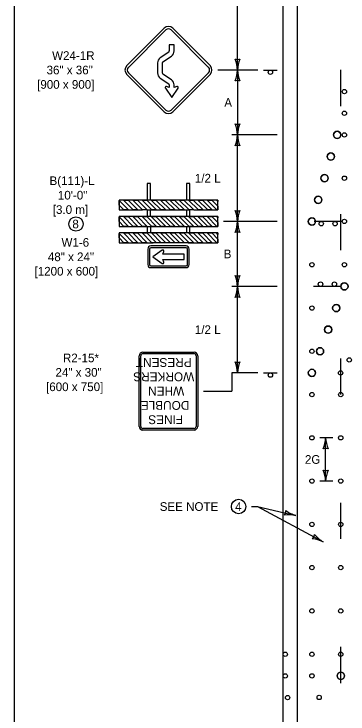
# Model space of a CAD drawing. Extents: x 49991.4 to 50021, y 49987.6 to 50011.4.
# Drawn here: x 50000.336 to 50002.651, y 50003.757 to 50008.61 of the extents above; entities that cross this region are included whole.
import ezdxf

# ---------------------------------------------------------------- set-up
doc = ezdxf.new("R2010")
doc.units = 0
for name, color, linetype in [('Level 1', 7, 'Continuous'), ('Level 2', 7, 'Continuous'), ('Level 3', 7, 'Continuous')]:
    doc.layers.add(name, color=color, linetype=linetype)

msp = doc.modelspace()

# ---------------------------------------------------------------- linework, layer by layer
at = {"layer": 'Level 1'}
for p, q in [((50002.201, 50000.5714), (50002.201, 50010.7538)), ((50002.301, 50000.5714), (50002.301, 50010.7538)), ((50001.4455, 50008.3968), (50001.412, 50008.3968)), ((50001.412, 50008.3968), (50001.412, 50008.3543)), ((50001.4455, 50008.3533), (50001.4455, 50008.3968)), ((50001.4078, 50008.3459), (50001.3492, 50008.3061)), ((50001.3681, 50008.2784), (50001.4267, 50008.3182)), ((50001.3304, 50008.2705), (50001.3305, 50008.2007)), ((50001.364, 50008.2007), (50001.3639, 50008.2705)), ((50001.4264, 50008.1537), (50001.3681, 50008.1928)), ((50002.065, 50008.2213), (50002.161, 50008.2213)), ((50002.601, 50007.9716), (50002.601, 50008.2216)), ((50001.3495, 50008.165), (50001.4078, 50008.1259)), ((50001.3847, 50008.096), (50001.4287, 50008.0319)), ((50001.412, 50008.1), (50001.3922, 50008.1062)), ((50001.412, 50008.118), (50001.412, 50008.1)), ((50001.4287, 50008.0319), (50001.4728, 50008.096)), ((50001.4455, 50008.1), (50001.4455, 50008.118)), ((50001.4653, 50008.1062), (50001.4455, 50008.1)), ((50001.0644, 50007.317), (50001.1302, 50007.2511)), ((50001.0644, 50007.317), (50001.1302, 50007.2511)), ((50001.0941, 50007.3195), (50001.1625, 50007.2511)), ((50001.1625, 50007.2511), (50001.0941, 50007.3195)), ((50001.1263, 50007.3195), (50001.1947, 50007.2511)), ((50001.1263, 50007.3195), (50001.1947, 50007.2511)), ((50001.1585, 50007.3195), (50001.2269, 50007.2511)), ((50001.2269, 50007.2511), (50001.1585, 50007.3195)), ((50001.1908, 50007.3195), (50001.2592, 50007.2511)), ((50001.1908, 50007.3195), (50001.2592, 50007.2511)), ((50001.223, 50007.3195), (50001.2914, 50007.2511)), ((50001.2914, 50007.2511), (50001.223, 50007.3195)), ((50001.2553, 50007.3195), (50001.3237, 50007.2511)), ((50001.2553, 50007.3195), (50001.3237, 50007.2511)), ((50001.2875, 50007.3195), (50001.3559, 50007.2511)), ((50001.3559, 50007.2511), (50001.2875, 50007.3195)), ((50001.3197, 50007.3195), (50001.3881, 50007.2511)), ((50001.3197, 50007.3195), (50001.3881, 50007.2511)), ((50001.3519, 50007.3195), (50001.4203, 50007.2511)), ((50001.4203, 50007.2511), (50001.3519, 50007.3195)), ((50001.3842, 50007.3195), (50001.4526, 50007.2511)), ((50001.3842, 50007.3195), (50001.4526, 50007.2511)), ((50001.4165, 50007.3195), (50001.4849, 50007.2511)), ((50001.4849, 50007.2511), (50001.4165, 50007.3195)), ((50001.4487, 50007.3195), (50001.5171, 50007.2511)), ((50001.4487, 50007.3195), (50001.5171, 50007.2511)), ((50001.4809, 50007.3195), (50001.5493, 50007.2511)), ((50001.5493, 50007.2511), (50001.4809, 50007.3195)), ((50001.5131, 50007.3195), (50001.5815, 50007.2511)), ((50001.5131, 50007.3195), (50001.5815, 50007.2511)), ((50001.5454, 50007.3195), (50001.6138, 50007.2511)), ((50001.6138, 50007.2511), (50001.5454, 50007.3195)), ((50001.5777, 50007.3195), (50001.6461, 50007.2511)), ((50001.5777, 50007.3195), (50001.6461, 50007.2511)), ((50001.6099, 50007.3195), (50001.6783, 50007.2511)), ((50001.6783, 50007.2511), (50001.6099, 50007.3195)), ((50001.6421, 50007.3195), (50001.7105, 50007.2511)), ((50001.6421, 50007.3195), (50001.7105, 50007.2511)), ((50001.6744, 50007.3195), (50001.7428, 50007.2511)), ((50001.7428, 50007.2511), (50001.6744, 50007.3195)), ((50001.7066, 50007.3195), (50001.7484, 50007.2778)), ((50001.7066, 50007.3195), (50001.7484, 50007.2778)), ((50001.7389, 50007.3195), (50001.7484, 50007.31)), ((50001.7484, 50007.31), (50001.7389, 50007.3195)), ((50001.0644, 50007.2847), (50001.098, 50007.2511)), ((50001.098, 50007.2511), (50001.0644, 50007.2847)), ((50002.601, 50006.9716), (50002.601, 50007.2216)), ((50001.0644, 50007.203), (50001.1302, 50007.1372)), ((50001.0644, 50007.203), (50001.1302, 50007.1372)), ((50001.0644, 50007.1708), (50001.098, 50007.1372)), ((50001.098, 50007.1372), (50001.0644, 50007.1708)), ((50001.0941, 50007.2056), (50001.1625, 50007.1372)), ((50001.1625, 50007.1372), (50001.0941, 50007.2056)), ((50001.1263, 50007.2056), (50001.1947, 50007.1372)), ((50001.1263, 50007.2056), (50001.1947, 50007.1372)), ((50001.1585, 50007.2056), (50001.2269, 50007.1372)), ((50001.2269, 50007.1372), (50001.1585, 50007.2056)), ((50001.1908, 50007.2056), (50001.2592, 50007.1372)), ((50001.1908, 50007.2056), (50001.2592, 50007.1372)), ((50001.223, 50007.2056), (50001.2914, 50007.1372)), ((50001.2553, 50007.2056), (50001.3237, 50007.1372)), ((50001.2875, 50007.2056), (50001.3559, 50007.1372)), ((50001.3197, 50007.2056), (50001.3881, 50007.1372)), ((50001.3519, 50007.2056), (50001.4203, 50007.1372)), ((50001.3842, 50007.2056), (50001.4526, 50007.1372)), ((50001.4165, 50007.2056), (50001.4849, 50007.1372)), ((50001.4487, 50007.2056), (50001.5171, 50007.1372)), ((50001.4809, 50007.2056), (50001.5432, 50007.1433)), ((50001.5131, 50007.2056), (50001.5432, 50007.1755)), ((50001.5432, 50007.1755), (50001.5815, 50007.1372)), ((50001.5454, 50007.2056), (50001.6138, 50007.1372)), ((50001.6138, 50007.1372), (50001.5454, 50007.2056)), ((50001.5777, 50007.2056), (50001.6461, 50007.1372)), ((50001.5777, 50007.2056), (50001.6461, 50007.1372)), ((50001.6099, 50007.2056), (50001.6783, 50007.1372)), ((50001.6783, 50007.1372), (50001.6099, 50007.2056)), ((50001.6421, 50007.2056), (50001.7105, 50007.1372)), ((50001.6421, 50007.2056), (50001.7105, 50007.1372)), ((50001.6744, 50007.2056), (50001.7428, 50007.1372)), ((50001.7428, 50007.1372), (50001.6744, 50007.2056)), ((50001.7066, 50007.2056), (50001.7484, 50007.1638)), ((50001.7066, 50007.2056), (50001.7484, 50007.1638)), ((50001.7389, 50007.2056), (50001.7484, 50007.1961)), ((50001.7484, 50007.1961), (50001.7389, 50007.2056)), ((50002.5135, 50007.1714), (50002.4175, 50007.1714)), ((50002.6095, 50007.1714), (50002.5135, 50007.1714)), ((50001.281, 50007.1372), (50001.281, 50007.0916)), ((50001.5318, 50007.1372), (50001.5318, 50007.0916)), ((50001.5432, 50007.1433), (50001.5493, 50007.1372)), ((50001.0644, 50007.0891), (50001.1302, 50007.0232)), ((50001.0644, 50007.0891), (50001.1302, 50007.0232)), ((50001.0941, 50007.0916), (50001.1625, 50007.0232)), ((50001.1625, 50007.0232), (50001.0941, 50007.0916)), ((50001.1263, 50007.0916), (50001.1947, 50007.0232)), ((50001.1263, 50007.0916), (50001.1947, 50007.0232)), ((50001.1585, 50007.0916), (50001.2269, 50007.0232)), ((50001.2269, 50007.0232), (50001.1585, 50007.0916)), ((50001.1908, 50007.0916), (50001.2592, 50007.0232)), ((50001.1908, 50007.0916), (50001.2592, 50007.0232)), ((50001.223, 50007.0916), (50001.2914, 50007.0232)), ((50001.2553, 50007.0916), (50001.3237, 50007.0232)), ((50001.2877, 50007.0916), (50001.3561, 50007.0232)), ((50001.3199, 50007.0916), (50001.3883, 50007.0232)), ((50001.3521, 50007.0916), (50001.4205, 50007.0232)), ((50001.3843, 50007.0916), (50001.4527, 50007.0232)), ((50001.4165, 50007.0916), (50001.4849, 50007.0232)), ((50001.4487, 50007.0916), (50001.5171, 50007.0232)), ((50001.4809, 50007.0916), (50001.5493, 50007.0232)), ((50001.5131, 50007.0916), (50001.5815, 50007.0232)), ((50001.5454, 50007.0916), (50001.6138, 50007.0232)), ((50001.6138, 50007.0232), (50001.5454, 50007.0916)), ((50001.5777, 50007.0916), (50001.6461, 50007.0232)), ((50001.5777, 50007.0916), (50001.6461, 50007.0232)), ((50001.6099, 50007.0916), (50001.6783, 50007.0232)), ((50001.6783, 50007.0232), (50001.6099, 50007.0916)), ((50001.6421, 50007.0916), (50001.7105, 50007.0232)), ((50001.6421, 50007.0916), (50001.7105, 50007.0232)), ((50001.6744, 50007.0916), (50001.7428, 50007.0232)), ((50001.7428, 50007.0232), (50001.6744, 50007.0916)), ((50001.7066, 50007.0916), (50001.7484, 50007.0498)), ((50001.7066, 50007.0916), (50001.7484, 50007.0498)), ((50001.7389, 50007.0916), (50001.7484, 50007.0821)), ((50001.7484, 50007.0821), (50001.7389, 50007.0916)), ((50001.0644, 50007.0568), (50001.098, 50007.0232)), ((50001.098, 50007.0232), (50001.0644, 50007.0568)), ((50001.2696, 50007.0232), (50001.3009, 50007.0232)), ((50001.5289, 50007.0232), (50001.2838, 50007.0232)), ((50001.5493, 50007.0232), (50001.5094, 50007.0232)), ((50001.2629, 50006.9805), (50001.2629, 50006.8722)), ((50001.2753, 50006.9805), (50001.2753, 50006.8722)), ((50001.5289, 50007.0014), (50001.2838, 50007.0014)), ((50001.5289, 50006.989), (50001.2838, 50006.989)), ((50001.3633, 50006.972), (50001.2969, 50006.9263)), ((50001.5375, 50006.8722), (50001.5375, 50006.9805)), ((50001.5499, 50006.8722), (50001.5499, 50006.9805)), ((50001.2969, 50006.9263), (50001.3633, 50006.8806)), ((50001.3675, 50006.9446), (50001.3739, 50006.9642)), ((50001.5159, 50006.9446), (50001.3675, 50006.9446)), ((50001.5159, 50006.9081), (50001.5159, 50006.9446)), ((50001.3739, 50006.8885), (50001.3675, 50006.9081)), ((50001.3675, 50006.9081), (50001.3777, 50006.9081)), ((50001.3777, 50006.9081), (50001.5159, 50006.9081)), ((50001.2838, 50006.8636), (50001.5289, 50006.8636)), ((50001.2838, 50006.8512), (50001.5289, 50006.8512)), ((50002.5085, 50006.7214), (50002.4125, 50006.7214)), ((50002.6045, 50006.7214), (50002.5085, 50006.7214)), ((50001.2292, 50006.2654), (50001.5836, 50006.2654)), ((50001.2292, 50006.2549), (50001.5836, 50006.2549)), ((50001.2039, 50005.7506), (50001.2039, 50006.2401)), ((50001.2144, 50005.7506), (50001.2144, 50006.2401)), ((50001.5984, 50006.2401), (50001.5984, 50005.7506)), ((50001.6089, 50006.2401), (50001.6089, 50005.7506)), ((50002.601, 50005.9716), (50002.601, 50006.2216)), ((50002.065, 50006.1214), (50002.161, 50006.1214)), ((50001.5836, 50005.7359), (50001.2292, 50005.7359)), ((50001.5836, 50005.7253), (50001.2292, 50005.7253)), ((50001.4064, 50005.7253), (50001.4064, 50005.7253)), ((50002.601, 50004.9716), (50002.601, 50005.2216)), ((50002.301, 50004.6448), (50002.301, 50004.6811)), ((50002.601, 50003.9716), (50002.601, 50004.2216))]:
    msp.add_line(p, q, dxfattribs=at)
msp.add_lwpolyline([(50008.6146, 50011.2628), (50000.3356, 50011.2628), (50000.3356, 50000.0624), (50008.6146, 50000.0624)], close=True, dxfattribs=at)
for points in [[(50001.1171, 50008.2515), (50001.3763, 50008.5106)], [(50001.1288, 50008.2399), (50001.3879, 50008.499)], [(50001.4249, 50008.499), (50001.684, 50008.2399)], [(50001.4365, 50008.5106), (50001.6956, 50008.2515)], [(50001.3763, 50007.9321), (50001.1171, 50008.1912)], [(50001.3879, 50007.9438), (50001.1288, 50008.2029)], [(50001.684, 50008.2029), (50001.4249, 50007.9438)], [(50001.6956, 50008.1912), (50001.4365, 50007.9321)], [(50001.281, 50007.3196), (50001.281, 50007.4336), (50001.2582, 50007.4336), (50001.2582, 50007.3196)], [(50001.5546, 50007.3196), (50001.5546, 50007.4336), (50001.5318, 50007.4336), (50001.5318, 50007.3196)], [(50001.5815, 50007.2511), (50001.7484, 50007.2511), (50001.7484, 50007.3195), (50001.0644, 50007.3195), (50001.0644, 50007.2511), (50001.2269, 50007.2511)], [(50001.0644, 50007.2847), (50001.0644, 50007.317)], [(50001.0941, 50007.3195), (50001.1263, 50007.3195)], [(50001.1585, 50007.3195), (50001.1908, 50007.3195)], [(50001.223, 50007.3195), (50001.2553, 50007.3195)], [(50001.2875, 50007.3195), (50001.3197, 50007.3195)], [(50001.3519, 50007.3195), (50001.3842, 50007.3195)], [(50001.4165, 50007.3195), (50001.4487, 50007.3195)], [(50001.4809, 50007.3195), (50001.5131, 50007.3195)], [(50001.5454, 50007.3195), (50001.5777, 50007.3195)], [(50001.6099, 50007.3195), (50001.6421, 50007.3195)], [(50001.6744, 50007.3195), (50001.7066, 50007.3195)], [(50001.7389, 50007.3195), (50001.7484, 50007.3195), (50001.7484, 50007.31)], [(50001.7484, 50007.2778), (50001.7484, 50007.2511), (50001.7428, 50007.2511)], [(50001.1302, 50007.2511), (50001.098, 50007.2511)], [(50001.1947, 50007.2511), (50001.1625, 50007.2511)], [(50001.2592, 50007.2511), (50001.2269, 50007.2511)], [(50001.2582, 50007.2511), (50001.2582, 50007.2056)], [(50001.2592, 50007.2511), (50001.5493, 50007.2511)], [(50001.281, 50007.2056), (50001.281, 50007.2511)], [(50001.3237, 50007.2511), (50001.2914, 50007.2511)], [(50001.3881, 50007.2511), (50001.3559, 50007.2511)], [(50001.4526, 50007.2511), (50001.4203, 50007.2511)], [(50001.5171, 50007.2511), (50001.4849, 50007.2511)], [(50001.5318, 50007.2511), (50001.5318, 50007.2056)], [(50001.5815, 50007.2511), (50001.5493, 50007.2511)], [(50001.5546, 50007.2056), (50001.5546, 50007.2511)], [(50001.6461, 50007.2511), (50001.6138, 50007.2511)], [(50001.7105, 50007.2511), (50001.6783, 50007.2511)], [(50001.5432, 50007.1372), (50001.7484, 50007.1372), (50001.7484, 50007.2056), (50001.0644, 50007.2056), (50001.0644, 50007.1372), (50001.5432, 50007.1372)], [(50001.0644, 50007.1708), (50001.0644, 50007.203)], [(50001.0941, 50007.2056), (50001.1263, 50007.2056)], [(50001.1585, 50007.2056), (50001.1908, 50007.2056)], [(50001.3237, 50007.1372), (50001.2914, 50007.1372), (50001.223, 50007.2056), (50001.2553, 50007.2056), (50001.3237, 50007.1372)], [(50001.3881, 50007.1372), (50001.3559, 50007.1372), (50001.2875, 50007.2056), (50001.3197, 50007.2056), (50001.3881, 50007.1372)], [(50001.4526, 50007.1372), (50001.4203, 50007.1372), (50001.3519, 50007.2056), (50001.3842, 50007.2056), (50001.4526, 50007.1372)], [(50001.5171, 50007.1372), (50001.4849, 50007.1372), (50001.4165, 50007.2056), (50001.4487, 50007.2056), (50001.5171, 50007.1372)], [(50001.4809, 50007.2056), (50001.5131, 50007.2056), (50001.5432, 50007.1755), (50001.5815, 50007.1372), (50001.5546, 50007.1372), (50001.5493, 50007.1372), (50001.5432, 50007.1433), (50001.4809, 50007.2056)], [(50001.5454, 50007.2056), (50001.5777, 50007.2056)], [(50001.6099, 50007.2056), (50001.6421, 50007.2056)], [(50001.6744, 50007.2056), (50001.7066, 50007.2056)], [(50001.7389, 50007.2056), (50001.7484, 50007.2056), (50001.7484, 50007.1961)], [(50001.7484, 50007.1638), (50001.7484, 50007.1372), (50001.7428, 50007.1372)], [(50001.1302, 50007.1372), (50001.098, 50007.1372)], [(50001.1947, 50007.1372), (50001.1625, 50007.1372)], [(50001.2592, 50007.1372), (50001.2269, 50007.1372)], [(50001.2582, 50007.1372), (50001.2582, 50007.0916)], [(50001.5546, 50007.0916), (50001.5546, 50007.1372)], [(50001.6461, 50007.1372), (50001.6138, 50007.1372)], [(50001.7105, 50007.1372), (50001.6783, 50007.1372)], [(50001.5432, 50007.0916), (50001.0644, 50007.0916), (50001.0644, 50007.0232), (50001.2696, 50007.0232)], [(50001.0644, 50007.0568), (50001.0644, 50007.0891)], [(50001.0941, 50007.0916), (50001.1263, 50007.0916)], [(50001.1585, 50007.0916), (50001.1908, 50007.0916)], [(50001.3237, 50007.0232), (50001.3009, 50007.0232), (50001.2914, 50007.0232), (50001.223, 50007.0916), (50001.2553, 50007.0916), (50001.3237, 50007.0232)], [(50001.3883, 50007.0232), (50001.3561, 50007.0232), (50001.2877, 50007.0916), (50001.3199, 50007.0916), (50001.3883, 50007.0232)], [(50001.4527, 50007.0232), (50001.4205, 50007.0232), (50001.3521, 50007.0916), (50001.3843, 50007.0916), (50001.4527, 50007.0232)], [(50001.5171, 50007.0232), (50001.5094, 50007.0232), (50001.4849, 50007.0232), (50001.4165, 50007.0916), (50001.4487, 50007.0916), (50001.5171, 50007.0232)], [(50001.4809, 50007.0916), (50001.5131, 50007.0916), (50001.5815, 50007.0232), (50001.5493, 50007.0232), (50001.4809, 50007.0916)], [(50001.5432, 50007.0232), (50001.7484, 50007.0232), (50001.7484, 50007.0916), (50001.5432, 50007.0916)], [(50001.5454, 50007.0916), (50001.5777, 50007.0916)], [(50001.6099, 50007.0916), (50001.6421, 50007.0916)], [(50001.6744, 50007.0916), (50001.7066, 50007.0916)], [(50001.7389, 50007.0916), (50001.7484, 50007.0916), (50001.7484, 50007.0821)], [(50001.1302, 50007.0232), (50001.098, 50007.0232)], [(50001.1947, 50007.0232), (50001.1625, 50007.0232)], [(50001.2592, 50007.0232), (50001.2269, 50007.0232)], [(50001.6461, 50007.0232), (50001.6138, 50007.0232)], [(50001.7105, 50007.0232), (50001.6783, 50007.0232)], [(50001.7484, 50007.0498), (50001.7484, 50007.0232), (50001.7428, 50007.0232)]]:
    msp.add_lwpolyline(points, dxfattribs=at)
for centre, radius in [((50002.113, 50008.2061), 0.0152), ((50002.626, 50008.0714), 0.015), ((50002.626, 50007.9214), 0.015), ((50002.576, 50007.7714), 0.025), ((50002.626, 50007.7714), 0.015), ((50002.5322, 50007.6214), 0.025), ((50002.4885, 50007.4714), 0.025), ((50002.626, 50007.4714), 0.015), ((50002.4447, 50007.3214), 0.025), ((50002.401, 50007.1714), 0.025), ((50002.4655, 50007.1561), 0.0152), ((50002.5615, 50007.1561), 0.0152), ((50002.626, 50007.1714), 0.015), ((50002.401, 50006.8714), 0.015), ((50002.626, 50006.8714), 0.015), ((50002.4605, 50006.7367), 0.0152), ((50002.5565, 50006.7367), 0.0152), ((50002.626, 50006.7214), 0.025), ((50002.401, 50006.5714), 0.015), ((50002.5697, 50006.5714), 0.025), ((50002.5135, 50006.4214), 0.025), ((50002.4572, 50006.2714), 0.025), ((50002.401, 50006.2714), 0.015), ((50002.6594, 50006.2114), 0.015), ((50002.401, 50006.1214), 0.025), ((50002.113, 50006.1061), 0.0152), ((50002.5995, 50006.1214), 0.015), ((50002.401, 50005.9714), 0.015), ((50002.601, 50005.9714), 0.015), ((50002.401, 50005.6714), 0.015), ((50002.601, 50005.6714), 0.015), ((50002.401, 50005.3714), 0.015), ((50002.601, 50005.3714), 0.015), ((50002.401, 50005.0714), 0.015), ((50002.601, 50005.0714), 0.015), ((50002.401, 50004.7714), 0.015), ((50002.601, 50004.7714), 0.015), ((50002.401, 50004.4714), 0.015), ((50002.601, 50004.4714), 0.015), ((50002.216, 50004.1706), 0.015), ((50002.401, 50004.1714), 0.015), ((50002.601, 50004.1714), 0.015), ((50002.216, 50004.0206), 0.015), ((50002.401, 50004.0214), 0.015), ((50002.601, 50004.0214), 0.025), ((50002.2327, 50003.8706), 0.015), ((50002.4511, 50003.8714), 0.015)]:
    msp.add_circle(centre, radius, dxfattribs=at)
for centre, radius, start, end in [((50001.4064, 50008.4805), 0.0426, 45, 135), ((50001.4064, 50008.4805), 0.0262, 45, 135), ((50001.4025, 50008.3538), 0.00951, 304.2095, 2.7638), ((50001.4025, 50008.3538), 0.043, 304.2095, 360), ((50001.3734, 50008.2705), 0.043, 124.2095, 180.0482), ((50001.1473, 50008.2214), 0.0426, 135, 225), ((50001.1473, 50008.2214), 0.0262, 135, 225), ((50001.3734, 50008.2705), 0.00951, 124.2095, 180.0514), ((50001.6655, 50008.2214), 0.0262, 315, 45), ((50001.6655, 50008.2214), 0.0426, 315, 45), ((50001.3734, 50008.2007), 0.043, 180, 236.1761), ((50001.3734, 50008.2007), 0.00951, 180, 236.1761), ((50001.4025, 50008.118), 0.043, 360, 56.1761), ((50001.3902, 50008.0998), 0.0067, 72.6382, 214.5163), ((50001.4025, 50008.118), 0.00951, 0, 56.1761), ((50001.4673, 50008.0998), 0.0067, 325.4837, 107.3618), ((50001.4064, 50007.9623), 0.0262, 225, 315), ((50001.4064, 50007.9623), 0.0426, 225, 315), ((50002.576, 50007.7714), 0.025, 0, 180), ((50002.576, 50007.7714), 0.025, 180, 0), ((50002.5322, 50007.6214), 0.025, 0, 180), ((50002.5322, 50007.6214), 0.025, 180, 0), ((50002.4885, 50007.4714), 0.025, 0, 180), ((50002.4885, 50007.4714), 0.025, 180, 0), ((50002.4447, 50007.3214), 0.025, 0, 180), ((50002.4447, 50007.3214), 0.025, 180, 0), ((50002.401, 50007.1714), 0.025, 0, 180), ((50002.401, 50007.1714), 0.025, 180, 0), ((50001.2838, 50006.9805), 0.0209, 90, 180), ((50001.2838, 50006.9805), 0.00855, 90, 180), ((50001.3673, 50006.9663), 0.00695, 342.0418, 124.5194), ((50001.5289, 50006.9805), 0.0209, 0, 90), ((50001.5289, 50006.9805), 0.00855, 0, 90), ((50001.3673, 50006.8864), 0.00695, 235.4806, 17.9582), ((50001.2838, 50006.8722), 0.0209, 180, 270), ((50001.2838, 50006.8722), 0.00855, 180, 270), ((50001.5289, 50006.8722), 0.00855, 270, 360), ((50001.5289, 50006.8722), 0.0209, 270, 360), ((50002.626, 50006.7214), 0.025, 0, 180), ((50002.626, 50006.7214), 0.025, 180, 0), ((50002.5697, 50006.5714), 0.025, 0, 180), ((50002.5697, 50006.5714), 0.025, 180, 0), ((50002.5135, 50006.4214), 0.025, 0, 180), ((50002.5135, 50006.4214), 0.025, 180, 0), ((50002.4572, 50006.2714), 0.025, 0, 180), ((50001.2292, 50006.2401), 0.0253, 90, 180), ((50001.2292, 50006.2401), 0.0148, 90, 180), ((50001.5836, 50006.2401), 0.0253, 360, 90), ((50001.5836, 50006.2401), 0.0148, 360, 90), ((50002.4572, 50006.2714), 0.025, 180, 0), ((50002.401, 50006.1214), 0.025, 0, 180), ((50002.401, 50006.1214), 0.025, 180, 0), ((50001.2292, 50005.7506), 0.0253, 180, 270), ((50001.2292, 50005.7506), 0.0148, 180, 270), ((50001.5836, 50005.7506), 0.0148, 270, 360), ((50001.5836, 50005.7506), 0.0253, 270, 360), ((50002.601, 50004.0214), 0.025, 0, 180), ((50002.601, 50004.0214), 0.025, 180, 0)]:
    msp.add_arc(centre, radius, start, end, dxfattribs=at)
at = {"layer": 'Level 2'}
for centre, radius in [((50000.7652, 50007.1536), 0.0499), ((50001.8928, 50005.1951), 0.0501)]:
    msp.add_circle(centre, radius, dxfattribs=at)
at = {"layer": 'Level 3'}
for p, q in [((50001.885, 50008.2214), (50001.885, 50009.709)), ((50002.025, 50008.2214), (50001.7481, 50008.2214)), ((50001.885, 50008.2214), (50001.885, 50007.7714)), ((50002.161, 50007.7714), (50001.845, 50007.7714)), ((50001.885, 50007.1714), (50001.885, 50007.7714)), ((50002.161, 50007.1714), (50001.7884, 50007.1714)), ((50001.885, 50006.7214), (50001.885, 50007.1714)), ((50002.161, 50006.7214), (50001.845, 50006.7214)), ((50001.885, 50006.1214), (50001.885, 50006.7214)), ((50001.885, 50006.1214), (50001.845, 50006.1214)), ((50001.845, 50006.1214), (50001.845, 50005.9953)), ((50002.025, 50006.1214), (50001.885, 50006.1214)), ((50001.6489, 50005.9953), (50001.845, 50005.9953)), ((50002.546, 50005.6714), (50002.456, 50005.6714)), ((50002.496, 50005.3714), (50002.496, 50005.6714)), ((50002.546, 50005.3714), (50002.456, 50005.3714)), ((50001.9829, 50005.1951), (50002.0229, 50005.1951)), ((50002.0229, 50005.1951), (50002.2894, 50005.1341)), ((50002.0229, 50005.1951), (50002.4784, 50004.9505))]:
    msp.add_line(p, q, dxfattribs=at)
for centre, radius, start, end in [((50001.6629, 50008.2122), 0.2223, 2.3605, 22.544), ((50001.885, 50008.3496), 0.0548, 252.1388, 287.8612), ((50002.1177, 50008.2099), 0.233, 157.9228, 177.1727), ((50001.6523, 50008.2329), 0.233, 337.9228, 357.1727), ((50002.1071, 50008.2305), 0.2223, 182.3605, 202.544), ((50001.885, 50008.0932), 0.0548, 72.1388, 107.8612), ((50001.6629, 50007.7622), 0.2223, 2.3605, 22.544), ((50001.885, 50007.8996), 0.0548, 252.1388, 287.8612), ((50002.1177, 50007.7599), 0.233, 157.9228, 177.1727), ((50001.6523, 50007.7829), 0.233, 337.9228, 357.1727), ((50002.1071, 50007.7805), 0.2223, 182.3605, 202.544), ((50001.885, 50007.6432), 0.0548, 72.1388, 107.8612), ((50001.6629, 50007.1622), 0.2223, 2.3605, 22.544), ((50001.885, 50007.2996), 0.0548, 252.1388, 287.8612), ((50002.1177, 50007.1599), 0.233, 157.9228, 177.1727), ((50001.6523, 50007.1829), 0.233, 337.9228, 357.1727), ((50002.1071, 50007.1805), 0.2223, 182.3605, 202.544), ((50001.885, 50007.0432), 0.0548, 72.1388, 107.8612), ((50001.6629, 50006.7122), 0.2223, 2.3605, 22.544), ((50001.885, 50006.8496), 0.0548, 252.1388, 287.8612), ((50002.1177, 50006.7099), 0.233, 157.9228, 177.1727), ((50001.6523, 50006.7329), 0.233, 337.9228, 357.1727), ((50002.1071, 50006.7305), 0.2223, 182.3605, 202.544), ((50001.885, 50006.5932), 0.0548, 72.1388, 107.8612), ((50001.6629, 50006.1122), 0.2223, 2.3605, 22.544), ((50001.885, 50006.2496), 0.0548, 252.1388, 287.8612), ((50002.1177, 50006.1099), 0.233, 157.9228, 177.1727), ((50002.2739, 50005.6805), 0.2223, 337.456, 357.6395), ((50002.7287, 50005.6829), 0.233, 182.8273, 202.0772), ((50002.496, 50005.5432), 0.0548, 72.1388, 107.8612), ((50002.496, 50005.4996), 0.0548, 252.1388, 287.8612), ((50002.2633, 50005.3599), 0.233, 2.8273, 22.0772), ((50002.7181, 50005.3622), 0.2223, 157.456, 177.6395), ((50002.1645, 50005.1627), 0.0548, 329.2424, 4.9647), ((50002.2487, 50004.9047), 0.233, 79.9309, 99.1807), ((50002.3479, 50005.3486), 0.2223, 234.5596, 254.7431), ((50002.3654, 50005.0112), 0.0548, 313.9028, 349.6252), ((50002.5915, 50005.1419), 0.2223, 219.22, 239.4035), ((50002.3784, 50004.7401), 0.233, 64.5913, 83.8411)]:
    msp.add_arc(centre, radius, start, end, dxfattribs=at)

# ---------------------------------------------------------------- texts
at = {"layer": 'Level 1'}
for s, p in [('PRESENT', (50001.5669, 50006.2243)), ('WORKERS', (50001.585, 50006.1251)), ('WHEN ', (50001.5155, 50006.026)), ('DOUBLE', (50001.551, 50005.9268)), ('FINES', (50001.5075, 50005.8277))]:
    msp.add_text(s, height=0.06118, rotation=180, dxfattribs=at).set_placement(p)
at = {"layer": 'Level 2'}
for s, p in [('W24-1R', (50000.5997, 50008.2914)), ('36" x 36"', (50000.5615, 50008.1914)), ('[900 x 900]', (50000.496, 50008.0914)), (' 1/2 L', (50001.5671, 50007.4414)), ('B(111)-L', (50000.5819, 50007.4236)), ('10\'-0"', (50000.6398, 50007.3236)), ('[3.0 m]', (50000.6045, 50007.2236)), ('8', (50000.7402, 50007.1236)), ('W1-6', (50000.6648, 50006.9963)), ('48" x 24"', (50000.5704, 50006.8963)), ('[1200 x 600]', (50000.4779, 50006.7963)), (' 1/2 L', (50001.5671, 50006.3914)), ('R2-15*', (50000.6748, 50006.1953)), ('24" x 30"', (50000.6232, 50006.0953)), ('[600 x 750]', (50000.5577, 50005.9953)), ('2G', (50002.3523, 50005.4914)), ('SEE NOTE', (50001.3458, 50005.1651)), ('4', (50001.8688, 50005.1651))]:
    msp.add_text(s, height=0.06, dxfattribs=at).set_placement(p)
for s, p in [('A', (50001.7935, 50007.9664)), ('B', (50001.7895, 50006.9164))]:
    msp.add_text(s, height=0.06, rotation=360, dxfattribs=at).set_placement(p)

doc.saveas('drawing.dxf')
